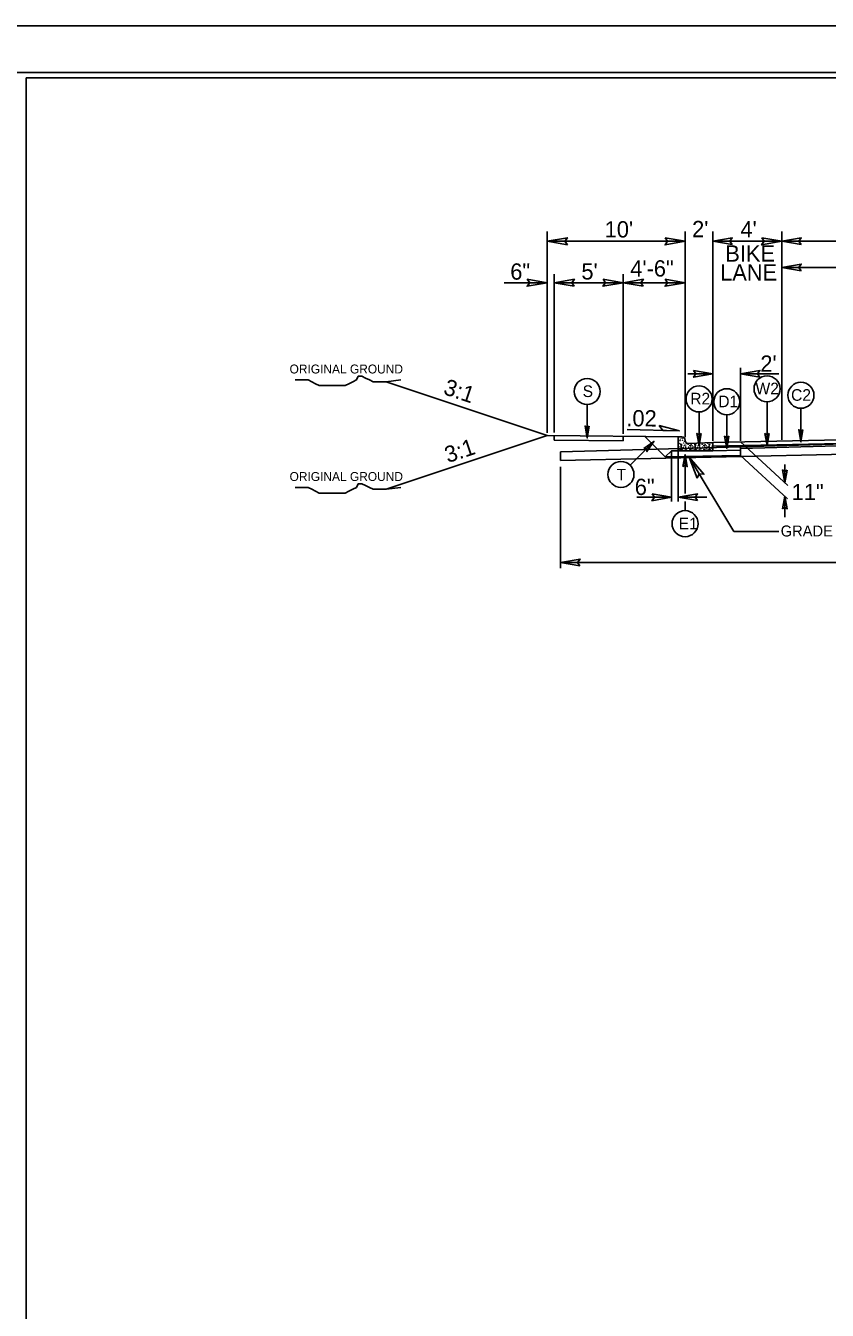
# Model space of a CAD drawing. Extents: x 957297 to 961629, y 830661 to 840840.
# Drawn here: x 958878 to 959261, y 839001 to 839615 of the extents above; entities that cross this region are included whole.
import ezdxf

# ---------------------------------------------------------------- set-up
doc = ezdxf.new("R2010")
doc.units = 0
for name, color, linetype in [('Old_Level_1', 7, 'Continuous'), ('Old_Level_11', 7, 'Continuous'), ('Old_Level_21', 7, 'Continuous'), ('Old_Level_3', 7, 'Continuous'), ('Prop CMT Pvmt Milling', 7, 'Continuous'), ('Prop Dimension Text', 7, 'Continuous'), ('Sheet Plot Border Inside CELL', 7, 'Continuous'), ('Sheet Plot Border Outside CELL', 7, 'Continuous'), ('Sheet Typical CELL', 7, 'Continuous'), ('Typical ID Circle CELL', 7, 'Continuous'), ('Typical Terminator CELL', 7, 'Continuous'), ('Typical Text ID Circle CELL', 7, 'Continuous')]:
    doc.layers.add(name, color=color, linetype=linetype)

msp = doc.modelspace()

# ---------------------------------------------------------------- linework, layer by layer
at = {"layer": 'Old_Level_1'}
for p, q in [((959127.17, 839420.51), (959127.17, 839516.83)), ((959193.21, 839418.52), (959193.21, 839516.83)), ((959206.42, 839416.67), (959206.42, 839516.83)), ((959239.42, 839516.83), (959239.42, 839417.22)), ((959127.17, 839512.21), (959193.21, 839512.21)), ((959206.42, 839512.21), (959239.42, 839512.21)), ((959239.42, 839512.21), (959494.54, 839512.21)), ((959130.47, 839496.52), (959130.47, 839420.65)), ((959163.49, 839496.52), (959163.49, 839420.02)), ((959239.42, 839499.67), (959332.9, 839499.67)), ((959127.17, 839492.35), (959106.5, 839492.35)), ((959130.47, 839492.35), (959163.49, 839492.35)), ((959163.49, 839492.35), (959193.21, 839492.35)), ((959194.48, 839448.72), (959206.42, 839448.72)), ((959219.62, 839416.76), (959219.62, 839451.65)), ((959219.62, 839448.72), (959237.94, 839448.72)), ((959127.17, 839419.21), (959049.98, 839444.94)), ((959049.98, 839393.48), (959127.17, 839419.21)), ((959127.17, 839419.21), (959190.13, 839418.58)), ((959130.47, 839419.18), (959130.47, 839417)), ((959130.47, 839417), (959163.49, 839416.67)), ((959163.49, 839418.84), (959163.49, 839416.67)), ((959165.47, 839422.05), (959190.45, 839421.55)), ((959183.65, 839408.99), (959173.9, 839418.74)), ((959494.54, 839421.75), (959206.42, 839415.93)), ((959494.54, 839420.03), (959206.42, 839414.2)), ((959219.62, 839416.2), (959242.32, 839395.31)), ((959133.56, 839407.25), (959133.55, 839411.5)), ((959186.54, 839411.88), (959183.65, 839408.99)), ((959189.84, 839411.95), (959186.54, 839411.88)), ((959186.54, 839387.73), (959186.54, 839411.68)), ((959189.84, 839387.73), (959189.84, 839411.68)), ((959219.62, 839412.21), (959206.42, 839411.95)), ((959219.62, 839413.84), (959219.62, 839409.72)), ((959133.56, 839404.27), (959133.56, 839355.68)), ((959219.62, 839409.72), (959183.65, 839408.99)), ((959216.4, 839373.28), (959195, 839408.87)), ((959219.62, 839409.72), (959242.13, 839389)), ((959240.87, 839405.32), (959240.87, 839396.65)), ((959169.94, 839389.68), (959186.54, 839389.68)), ((959189.84, 839389.68), (959203.57, 839389.68)), ((959240.85, 839390.18), (959240.85, 839380.22)), ((959216.4, 839373.28), (959237.91, 839373.28)), ((959133.56, 839358.46), (959479.39, 839358.46))]:
    msp.add_line(p, q, dxfattribs=at)
for points in [[(959219.62, 839413.84), (959133.55, 839411.5)], [(959133.56, 839407.25), (959306.49, 839411.18)]]:
    msp.add_lwpolyline(points, dxfattribs=at)
at = {"layer": 'Old_Level_11'}
for p, q in [((959182.44, 839421.71), (959180.71, 839423.96)), ((959180.71, 839423.96), (959190.45, 839421.55)), ((959190.45, 839421.55), (959182.44, 839421.71))]:
    msp.add_line(p, q, dxfattribs=at)
for points in [[(959136.78, 839510.55), (959127.17, 839512.21), (959136.83, 839513.91), (959135.61, 839512.21)], [(959183.6, 839513.86), (959193.21, 839512.21), (959183.54, 839510.49), (959184.77, 839512.21)], [(959229.81, 839513.86), (959239.42, 839512.21), (959229.75, 839510.49), (959230.98, 839512.21)], [(959117.56, 839494.01), (959127.17, 839492.35), (959117.5, 839490.64), (959118.73, 839492.35)], [(959140.08, 839490.7), (959130.47, 839492.35), (959140.13, 839494.06), (959138.91, 839492.35)], [(959153.88, 839494.01), (959163.49, 839492.35), (959153.82, 839490.64), (959155.05, 839492.35)], [(959173.1, 839490.7), (959163.49, 839492.35), (959173.15, 839494.06), (959171.93, 839492.35)], [(959183.6, 839494.01), (959193.21, 839492.35), (959183.54, 839490.64), (959184.77, 839492.35)], [(959198.88, 839398.87), (959195, 839408.87), (959202.09, 839400.73), (959199.78, 839400.92)]]:
    msp.add_lwpolyline(points, close=True, dxfattribs=at)
at = {"layer": 'Old_Level_21'}
for points in [[(959057.08, 839445.82), (959049.98, 839444.94), (959048.21, 839444.94), (959045.55, 839444.94), (959043.77, 839444.94), (959042, 839445.82), (959040.22, 839446.72), (959038.45, 839447.6), (959036.68, 839447.6), (959035.78, 839445.82), (959034.02, 839444.94), (959032.24, 839444.04), (959030.47, 839443.17), (959028.7, 839443.17), (959026.93, 839443.17), (959025.15, 839443.17), (959023.38, 839443.17), (959021.6, 839443.17), (959019.83, 839443.17), (959018.05, 839443.17), (959016.29, 839444.04), (959014.52, 839444.94), (959012.75, 839445.82), (959010.07, 839445.82), (959008.3, 839445.82), (959006.53, 839445.82)], [(959057.08, 839394.36), (959049.98, 839393.48), (959048.21, 839393.48), (959045.55, 839393.48), (959043.77, 839393.48), (959042, 839394.36), (959040.22, 839395.25), (959038.45, 839396.14), (959036.68, 839396.14), (959035.78, 839394.36), (959034.02, 839393.48), (959032.24, 839392.58), (959030.47, 839391.71), (959028.7, 839391.71), (959026.93, 839391.71), (959025.15, 839391.71), (959023.38, 839391.71), (959021.6, 839391.71), (959019.83, 839391.71), (959018.05, 839391.71), (959016.29, 839392.58), (959014.52, 839393.48), (959012.75, 839394.36), (959010.07, 839394.36), (959008.3, 839394.36), (959006.53, 839394.36)]]:
    msp.add_lwpolyline(points, dxfattribs=at)
at = {"layer": 'Old_Level_3'}
for p, q in [((959189.84, 839415.26), (959189.84, 839418.3)), ((959190.13, 839418.58), (959191.5, 839418.58)), ((959193.29, 839416.53), (959193.18, 839416.39)), ((959193.18, 839416.39), (959193.33, 839416.42)), ((959189.84, 839411.95), (959189.84, 839415.26)), ((959206.42, 839411.95), (959189.84, 839411.95)), ((959191.03, 839412.33), (959191.5, 839412.98)), ((959191.67, 839412.36), (959191.03, 839412.33)), ((959191.12, 839415.03), (959191.12, 839414.45)), ((959191.7, 839415), (959191.12, 839415.03)), ((959191.12, 839414.45), (959191.7, 839415)), ((959191.5, 839412.98), (959191.67, 839412.36)), ((959194.88, 839415.35), (959206.42, 839415.93)), ((959194.88, 839415.35), (959194.88, 839415.35)), ((959195.15, 839412.06), (959195.49, 839412.67)), ((959196.04, 839412.27), (959195.15, 839412.06)), ((959195.34, 839414.63), (959195.43, 839414.14)), ((959196.16, 839414.39), (959195.34, 839414.63)), ((959195.43, 839414.14), (959196.16, 839414.39)), ((959195.49, 839412.67), (959196.04, 839412.27)), ((959197.76, 839412.33), (959198.22, 839412.98)), ((959198.4, 839412.36), (959197.76, 839412.33)), ((959197.85, 839415.03), (959197.85, 839414.45)), ((959198.43, 839415), (959197.85, 839415.03)), ((959197.85, 839414.45), (959198.43, 839415)), ((959198.22, 839412.98), (959198.4, 839412.36)), ((959201.88, 839412.06), (959202.22, 839412.67)), ((959202.78, 839412.27), (959201.88, 839412.06)), ((959202.06, 839414.63), (959202.16, 839414.14)), ((959202.9, 839414.39), (959202.06, 839414.63)), ((959202.16, 839414.14), (959202.9, 839414.39)), ((959202.22, 839412.67), (959202.78, 839412.27)), ((959204.49, 839412.33), (959204.95, 839412.98)), ((959205.13, 839412.36), (959204.49, 839412.33)), ((959204.58, 839415.03), (959204.58, 839414.45)), ((959205.16, 839415), (959204.58, 839415.03)), ((959204.58, 839414.45), (959205.16, 839415)), ((959204.95, 839412.98), (959205.13, 839412.36)), ((959206.42, 839415.93), (959206.42, 839411.95))]:
    msp.add_line(p, q, dxfattribs=at)
for centre in [(959189.9, 839416.85), (959190.66, 839416.75), (959190.82, 839417.49), (959191.68, 839417.86), (959191.83, 839416.94), (959192.78, 839417.74), (959192.81, 839416.45), (959189.99, 839414.26), (959190.02, 839412.08), (959190.11, 839413.19), (959190.54, 839415.46), (959190.54, 839412.33), (959190.69, 839413.86), (959191.21, 839413.41), (959191.46, 839413.95), (959192.26, 839413.62), (959192.41, 839413.07), (959192.48, 839415.65), (959192.75, 839414.54), (959193.21, 839412.61), (959193.37, 839413.53), (959193.46, 839413.8), (959193.49, 839414.6), (959193.58, 839415.62), (959193.89, 839412.76), (959194.57, 839415), (959194.84, 839413.65), (959195.49, 839413.38), (959196.01, 839414.85), (959196.44, 839412.85), (959196.54, 839413.38), (959196.72, 839414.26), (959196.75, 839412.08), (959196.84, 839413.19), (959197.27, 839412.33), (959197.42, 839413.86), (959197.94, 839413.41), (959198.19, 839413.95), (959198.99, 839413.62), (959199.14, 839413.07), (959199.48, 839414.54), (959199.94, 839412.61), (959200.1, 839413.53), (959200.19, 839413.8), (959200.22, 839414.6), (959200.62, 839412.76), (959201.3, 839415), (959201.57, 839413.65), (959202.22, 839413.38), (959202.74, 839414.85), (959203.17, 839412.85), (959203.26, 839413.38), (959203.45, 839414.26), (959203.48, 839412.08), (959203.56, 839413.19), (959204, 839415.46), (959204, 839412.33), (959204.15, 839413.86), (959204.67, 839413.41), (959204.92, 839413.95), (959205.72, 839413.62), (959205.87, 839413.07), (959205.93, 839415.65), (959206.21, 839414.54)]:
    msp.add_circle(centre, 0.0432, dxfattribs=at)
for centre, radius, start, end in [((959190.13, 839418.29), 0.287, 90, 180), ((959190.02, 839418.51), 0.0432, 259.65309, 10.34691), ((959191.5, 839416.92), 1.66, 1.07335, 90), ((959194.79, 839416.99), 1.64, 181.07335, 272.86241), ((959189.81, 839413.38), 0.0432, 330.41728, 29.58272), ((959197.27, 839415.46), 0.0432, 167.77954, 17.93798), ((959200.31, 839415.62), 0.0432, 169.83737, 15.88014)]:
    msp.add_arc(centre, radius, start, end, dxfattribs=at)
at = {"layer": 'Prop CMT Pvmt Milling'}
for p, q in [((959219.62, 839413.84), (959306.49, 839416.22)), ((959219.62, 839412.98), (959219.62, 839413.84))]:
    msp.add_line(p, q, dxfattribs=at)
msp.add_lwpolyline([(959306.49, 839416.22), (959306.46, 839415.36), (959219.62, 839412.98)], dxfattribs=at)
at = {"layer": 'Sheet Plot Border Inside CELL'}
msp.add_lwpolyline([(960390.3, 839592.94), (958723.8, 839592.94), (958723.8, 838537.84), (960390.3, 838537.84)], close=True, dxfattribs=at)
at = {"layer": 'Sheet Plot Border Outside CELL'}
msp.add_lwpolyline([(960394.8, 839615.39), (958710.8, 839615.39), (958710.8, 838515.39), (960394.8, 838515.39)], close=True, dxfattribs=at)
at = {"layer": 'Sheet Typical CELL'}
msp.add_lwpolyline([(960377.8, 839590.39), (958877.8, 839590.39), (958877.8, 838540.39), (960377.8, 838540.39)], close=True, dxfattribs=at)
at = {"layer": 'Typical ID Circle CELL'}
for p, q in [((959232.33, 839435.36), (959232.33, 839414.39)), ((959146.26, 839434.06), (959146.26, 839417.97)), ((959199.79, 839430.51), (959199.79, 839414.42)), ((959213.06, 839429.18), (959213.06, 839413.09)), ((959248.55, 839432.27), (959248.55, 839416.18)), ((959166.83, 839405.01), (959178.2, 839416.39)), ((959193.1, 839391.52), (959193.1, 839410.13)), ((959193.1, 839383.26), (959193.1, 839387.62))]:
    msp.add_line(p, q, dxfattribs=at)
for centre in [(959232.33, 839441.58), (959146.26, 839440.29), (959199.79, 839436.73), (959213.06, 839435.4), (959248.55, 839438.49), (959162.43, 839400.61), (959193.1, 839377.04)]:
    msp.add_circle(centre, 6.23, dxfattribs=at)
at = {"layer": 'Typical Terminator CELL'}
for points in [[(959215.64, 839510.62), (959206.42, 839512.21), (959215.69, 839513.85), (959214.51, 839512.21)], [(959248.64, 839510.62), (959239.42, 839512.21), (959248.69, 839513.85), (959247.51, 839512.21)], [(959248.64, 839498.08), (959239.42, 839499.67), (959248.69, 839501.3), (959247.51, 839499.67)], [(959197.19, 839450.31), (959206.42, 839448.72), (959197.14, 839447.09), (959198.32, 839448.72)], [(959228.84, 839447.14), (959219.62, 839448.72), (959228.89, 839450.36), (959227.72, 839448.72)], [(959147.26, 839423.74), (959146.26, 839417.97), (959145.24, 839423.77), (959146.26, 839423.03)], [(959173.42, 839413.01), (959178.2, 839416.39), (959174.83, 839411.57), (959174.62, 839412.81)], [(959200.79, 839420.19), (959199.79, 839414.42), (959198.77, 839420.22), (959199.79, 839419.48)], [(959214.05, 839418.85), (959213.06, 839413.09), (959212.03, 839418.89), (959213.06, 839418.15)], [(959233.33, 839420.15), (959232.33, 839414.39), (959231.31, 839420.18), (959232.33, 839419.45)], [(959249.54, 839421.94), (959248.55, 839416.18), (959247.52, 839421.98), (959248.55, 839421.24)], [(959192.1, 839404.37), (959193.1, 839410.13), (959194.12, 839404.33), (959193.1, 839405.07)], [(959241.91, 839402.71), (959240.87, 839396.65), (959239.79, 839402.75), (959240.87, 839401.97)], [(959177.32, 839391.27), (959186.54, 839389.68), (959177.27, 839388.04), (959178.45, 839389.68)], [(959199.07, 839388.1), (959189.84, 839389.68), (959199.12, 839391.32), (959197.94, 839389.68)], [(959239.81, 839384.11), (959240.85, 839390.18), (959241.93, 839384.08), (959240.85, 839384.86)], [(959142.78, 839356.87), (959133.56, 839358.46), (959142.83, 839360.1), (959141.65, 839358.46)]]:
    msp.add_lwpolyline(points, close=True, dxfattribs=at)

# ---------------------------------------------------------------- texts
at = {"layer": 'Old_Level_1'}
msp.add_text('GRADE TO THIS LINE', height=5.2473, dxfattribs=at).set_placement((959238.87, 839370.91))
at = {"layer": 'Old_Level_21'}
for p in [(959003.82, 839448.93), (959003.82, 839397.47)]:
    msp.add_text('ORIGINAL GROUND', height=4.2722, dxfattribs=at).set_placement(p)
at = {"layer": 'Old_Level_3'}
for s, p in [("10'", (959154.64, 839514.02)), ("2'", (959196.48, 839514.16)), ("4'", (959219.61, 839514.03)), ('BIKE', (959212.37, 839502.47)), ('4\'-6"', (959166.89, 839495.32)), ('6"', (959109.45, 839493.83)), ("5'", (959143.5, 839493.91)), ('LANE', (959209.92, 839493.37))]:
    msp.add_text(s, height=7.801, dxfattribs=at).set_placement(p)
for s, rotation, p in [('3:1', 341.56515, (959076.99, 839439.17)), ('.02', 359.43356, (959164.98, 839423.67)), ('3:1', 18.43485, (959079.57, 839406))]:
    msp.add_text(s, height=7.801, rotation=rotation, dxfattribs=at).set_placement(p)
at = {"layer": 'Prop Dimension Text'}
for s, p in [("2'", (959229.14, 839449.74)), ('6"', (959169.02, 839390.76)), ('11"', (959244.12, 839388.29))]:
    msp.add_text(s, height=7.801, rotation=0, dxfattribs=at).set_placement(p)
at = {"layer": 'Typical Text ID Circle CELL'}
for s, height, p in [('S', 5.57, (959144.09, 839437.66)), ('W2', 5.572, (959226.82, 839438.95)), ('C2', 5.572, (959243.84, 839435.86)), ('R2', 5.572, (959195.59, 839434.1)), ('D1', 5.572, (959209, 839432.77)), ('E1', 5.572, (959190.06, 839374.3))]:
    msp.add_text(s, height=height, dxfattribs=at).set_placement(p)
msp.add_text('T', height=5.57, rotation=360, dxfattribs=at).set_placement((959160.28, 839397.71))

doc.saveas('drawing.dxf')
